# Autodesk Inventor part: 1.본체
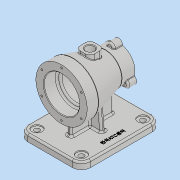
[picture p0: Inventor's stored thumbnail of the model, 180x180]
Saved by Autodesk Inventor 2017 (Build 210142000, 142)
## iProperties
Part Number: 1.본체
Material: 일반
Document SubType Name: Modeling
Designer: user
Density: 1 g/cm^3
Appearance: 기본값
Author: user
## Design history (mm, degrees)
sketch "스케치1"
  geometry: L1 (-50, 0)-(50, 0); L2 (-50, 0)-(-50, 45); L3 (-50, 45)-(-30, 45); L4 (-30, 45)-(27, 29); L5 (27, 29)-(50, 29); L6 (50, 29)-(50, 0); 2 further points
  constraints: 12 end point, 2 perpendicular, 1 coincident, 1 horizontal, 1 midpoint, 1 parallel, 1 vertical
  dimensions: "d0" = 100 distance of L1.start L1.end; "d1" = 45 distance of L1.start L2.end; "d2" = 20 distance of L2.end L3.end; "d3" = 58 diameter of L5 L1; "d4" = 23 distance of L4.end L5.end
revolve "회전1" sketch "스케치1" stored, may be unused: angle "d5" = 90 deg
node "작업 평면1"
sketch "스케치5" dims "d100" = 16
  geometry: L1 (-70, -55)-(70, -55); L2 (70, -55)-(70, 55); L3 (70, 55)-(-70, 55); L4 (-70, 55)-(-70, -55); L5 (-70, -55)-(70, 55); L6 (70, -55)-(-70, 55); 1 further point
  constraints: 12 end point, 2 midpoint, 2 parallel, 1 horizontal, 1 perpendicular
  dimensions: "d34" = 140 distance of L3.end L2.end; "d35" = 110 distance of L2.end L1.end
extrude "돌출2" join sketch "스케치5" distance "d36" = 12; taper "d37" = 0 deg
sketch "스케치6"
  geometry: L1 (-37, -4)-(37, -4); L2 (37, -4)-(37, 4); L3 (37, 4)-(-37, 4); L4 (-37, 4)-(-37, -4); L5 (-37, -4)-(37, 4); L6 (37, -4)-(-37, 4); 1 further point
  constraints: 12 end point, 2 midpoint, 2 parallel, 1 horizontal, 1 perpendicular
  dimensions: "d38" = 74 distance of L3.end L2.end; "d39" = 8 distance of L2.end L1.end
extrude "돌출3" join sketch "스케치6" distance "d40" = 82; taper "d41" = 0 deg
sketch "스케치7"
  geometry: L1 (-70, -55)-(-70, 55) reference; L2 (0, 0)-(-70, 0); L3 (-70, 0)-(-70, -24); L4 (-70, -24)-(-4.155, -18.239); L5 (-70, 0)-(-70, 24); L6 (-70, 24)-(-4.155, 18.239); L7 (-4.155, 18.239)-(-4.155, -18.239)
  constraints: 12 end point, 2 point on line, 1 midpoint, 1 vertical
  dimensions: "d42" = 24 distance of L2.end L3.end; "d43" = 24 distance of L2.end L5.end; "d44" = 95 deg angle of L1 L6; "d45" = 95 deg angle of L1 L4; "d46" = 36.47868 distance of L6.end L4.end
extrude "돌출4" join sketch "스케치7" stored distance "d47" = 8; taper "d48" = 0 deg
sketch "스케치8"
  geometry: L1 (0, 0)-(0, 29); L2 (0, 0)-(25.115, -14.5); L3 (0, 0)-(-25.115, -14.5); C1 r 7 at (0, 29); C2 r 7 at (25.115, -14.5); C3 r 7 at (-25.115, -14.5); A1 r 29 centre (0, 0) between (4, -28.723) and (-4, -28.723) reference; A2 r 29 centre (0, 0) between (0, 29) and (25.115, -14.5)
  constraints: 6 end point, 6 point on circle, 4 centre point, 4 coincident
  dimensions: "d49" = 120 deg angle of L2 L1; "d50" = 120 deg angle of L2 L3; "d51" = 14 diameter of C1; "d52" = 14 diameter of C2; "d53" = 14 diameter of C3
extrude "돌출5" join sketch "스케치8" distance "d54" = 15; taper "d55" = 0 deg
sketch "스케치9"
  geometry: A1 r 7 centre (25.115, -43.5) between (20.909, -49.095) and (27.858, -37.06) reference; A2 r 7 centre (-25.115, -43.5) between (-27.858, -37.06) and (-20.909, -49.095) reference; 3 further points
  constraints: 2 coincident
hole "구멍3" sketch "스케치9" at (0, 0), (25.115, -43.5), (-25.115, -43.5) diameter "d56" = 3.242; stored, may be unused: countersink angle "d60" = 90 deg, drill point angle "d62" = 118 deg; dims "d57" = 9, "d58" = 4, "d59" = 2, "d61" = 11
sketch "스케치10"
  geometry: L1 (0, 40)-(0, -40); L2 (-34.641, 20)-(34.641, -20); L3 (-34.641, -20)-(34.641, 20); L4 (0, -40)-(0, 40); L5 (34.641, -20)-(-34.641, 20); L6 (34.641, 20)-(-34.641, -20); C1 r 45 at (0, 0) reference; C2 r 40 at (0, 0); 18 further points
  constraints: 14 coincident, 12 end point, 1 centre point, 1 midpoint, 1 vertical, 37 other
  dimensions: "d63" = 80 diameter of C2; "d64" = 80 distance of L1.start L1.end; "d67" = 360 deg dimension on C1.centre point (0, 40) (derived)
hole "구멍4" sketch "스케치10" at (0, 40), (0, -40), (-34.641, 20), (34.641, -20), (-34.641, -20), (34.641, 20) diameter "d69" = 3.242; stored, may be unused: countersink angle "d73" = 90 deg, drill point angle "d75" = 118 deg; dims "d70" = 9, "d71" = 4, "d72" = 2, "d74" = 11
sketch "스케치11"
  geometry: L1 (-50, -45)-(-50, 45) reference; L2 (-50, 0)-(50, 0); L3 (50, -8.06)-(50, 28.155) reference; L4 (-50, 0)-(-50, 31); L5 (-50, 31)-(-27, 31); L6 (-27, 31)-(-27, 25); L7 (-27, 25)-(20, 25); L8 (20, 25)-(20, 19); L9 (20, 19)-(50, 19); L10 (50, 0)-(50, 19); 1 further point
  constraints: 16 end point, 5 perpendicular, 3 point on line, 1 collinear, 1 horizontal, 1 midpoint
  dimensions: "d76" = 31 distance of L2.start L4.end; "d77" = 23 distance of L4.end L5.end; "d78" = 47 distance of L6.end L7.end; "d79" = 50 diameter of L7 L2; "d80" = 38 diameter of L9 L2
revolve "회전2" sketch "스케치11" stored, may be unused: angle "d81" = 90 deg
node "작업 평면2"
sketch "스케치12"
  geometry: L1 (-12.5, -12.5)-(12.5, -12.5); L2 (12.5, -12.5)-(12.5, 12.5); L3 (12.5, 12.5)-(-12.5, 12.5); L4 (-12.5, 12.5)-(-12.5, -12.5); L5 (-12.5, -12.5)-(12.5, 12.5); L6 (12.5, -12.5)-(-12.5, 12.5); 1 further point
  constraints: 12 end point, 2 midpoint, 2 parallel, 1 horizontal, 1 perpendicular
  dimensions: "d83" = 25 distance of L3.end L2.end; "d84" = 25 distance of L2.end L1.end
extrude "돌출6" join sketch "스케치12" stored distance "d85" = 15; taper "d86" = 0 deg
sketch "스케치13"
  geometry: C1 r 7.5 at (0, 0); 1 further point
  constraints: 1 centre point, 1 coincident
  dimensions: "d87" = 15 diameter of C1
extrude "돌출7" cut sketch "스케치13" stored distance "d88" = 0; taper "d89" = 0 deg
fillet "모깎기1" dims "d90" = 8
chamfer "모따기1" distance "d91" = 1; stored, may be unused: second distance "d92" = 2, angle "d93" = 45 deg
fillet "모깎기2" dims "d94" = 3
fillet "모깎기3" dims "d95" = 1
fillet "모깎기4" dims "d96" = 3
fillet "모깎기5" dims "d97" = 3
fillet "모깎기6" dims "d98" = 3
fillet "모깎기7" dims "d99" = 3
fillet "모깎기8" dims "d100" = 16
sketch "스케치14"
  geometry: A1 r 16 centre (-54, -39) between (-70, -39) and (-54, -55) reference; A2 r 16 centre (54, -39) between (54, -55) and (70, -39) reference; A3 r 16 centre (54, 39) between (70, 39) and (54, 55) reference; A4 r 16 centre (-54, 39) between (-54, 55) and (-70, 39) reference; 5 further points
  constraints: 4 coincident
hole "구멍5" sketch "스케치14" at (54, 39), (54, -39), (-54, -39), (-54, 39) diameter "d101" = 9; stored, may be unused: countersink angle "d105" = 90 deg, drill point angle "d107" = 118 deg; dims "d102" = 9, "d103" = 18, "d104" = 2, "d106" = 30
fillet "모깎기9" dims "d108" = 3
chamfer "모따기2" distance "d109" = 1; stored, may be unused: second distance "d110" = 2, angle "d111" = 45 deg
chamfer "모따기3" distance "d112" = 1; stored, may be unused: second distance "d113" = 2, angle "d114" = 45 deg
sketch "스케치15"
  geometry: L1 (-7, 20.726)-(-7, 7) reference; L2 (1, 26.749)-(-1, 26.749) reference; L3 (7, 7)-(7, 20.726) reference; L4 (34, 7)-(7, 7) reference; L5 (40, -1)-(40, 1) reference; L6 (7, -7)-(34, -7) reference; L7 (7, -20.726)-(7, -7) reference; L8 (-1, -26.749)-(1, -26.749) reference; L9 (-7, -7)-(-7, -20.726) reference; L10 (-34, -7)-(-7, -7) reference; L11 (-40, 1)-(-40, -1) reference; L12 (-7, 7)-(-34, 7) reference; L13 (-54, -55)-(54, -55) reference; L14 (70, -39)-(70, 39) reference; L15 (54, 55)-(-54, 55) reference; L16 (-70, 39)-(-70, -39) reference; C1 r 9 at (-54, -39) reference; C2 r 9 at (54, 39) reference; C3 r 9 at (54, -39) reference; C4 r 9 at (-54, 39) reference; A1 r 6 centre (34, 1) between (40, 1) and (34, 7) reference; A2 r 6 centre (34, -1) between (34, -7) and (40, -1) reference; A3 r 6 centre (-34, -1) between (-40, -1) and (-34, -7) reference; A4 r 6 centre (-34, 1) between (-34, 7) and (-40, 1) reference; A5 r 16 centre (-54, -39) between (-70, -39) and (-54, -55) reference; A6 r 16 centre (54, -39) between (54, -55) and (70, -39) reference; A7 r 16 centre (54, 39) between (70, 39) and (54, 55) reference; A8 r 16 centre (-54, 39) between (-54, 55) and (-70, 39) reference; 5 further points; 4 other entities
  constraints: 4 other
sketch "스케치16"
  geometry: L1 (-70, -70)-(-70, -82) reference; L2 (-50, -45)-(-50, 45) reference; L3 (-37, -47.99)-(-37, -67) reference; L4 (37, -67)-(37, -31.984) reference; 1 further point
  dimensions: "d115" = 20 distance between parallel lines of L1 L2 (derived); "d116" = 33 distance between parallel lines of L1 L3 (derived); "d117" = 74 distance between parallel lines of L4 L3 (derived)
fillet "모깎기10" dims "d118" = 3
node "작업 평면3"
sketch "스케치17"
  geometry: L1 (54, 55)-(-54, 55) reference; L2 (0, 55)-(0, 40); 3 further points
  constraints: 2 coincident, 2 end point, 1 midpoint, 1 vertical, 1 other
  dimensions: "d120" = 15 distance of L2.start L2.end
feature "엠보싱1" sketch "스케치17" dims "d0" = 100, "d1" = 45, "d2" = 20, "d3" = 58, "d4" = 23, "d121" = 0.5, "d122" = 0
fillet "모깎기11" dims "d123" = 1
sketch "스케치18"
  geometry: L1 (0, -29)-(0, 26.077); L2 (0, -29)-(-47.698, -56.538); C1 r 1.621 at (-25.115, -43.5) reference; C2 r 1.621 at (0, 0) reference; C3 r 1.621 at (25.115, -43.5) reference; C4 r 20 at (0, -29) reference; A1 r 29 centre (0, -29) between (-20.339, -49.672) and (20.339, -49.672) reference; A2 r 1 centre (21.04, -50.385) between (21.55, -49.524) and (20.339, -49.672) reference; A3 r 7 centre (25.115, -43.5) between (21.55, -49.524) and (28.549, -37.4) reference; A4 r 1 centre (29.04, -36.529) between (28.072, -36.278) and (28.549, -37.4) reference; A5 r 29 centre (0, -29) between (28.072, -36.278) and (7.733, -1.05) reference; A6 r 1 centre (8, -0.086) between (7, -0.075) and (7.733, -1.05) reference; A7 r 7 centre (0, 0) between (7, -0.075) and (-7, -0.075) reference; A8 r 1 centre (-8, -0.086) between (-7.733, -1.05) and (-7, -0.075) reference; A9 r 29 centre (0, -29) between (-7.733, -1.05) and (-28.072, -36.278) reference; A10 r 1 centre (-29.04, -36.529) between (-28.549, -37.4) and (-28.072, -36.278) reference; A11 r 7 centre (-25.115, -43.5) between (-28.549, -37.4) and (-21.55, -49.524) reference; A12 r 1 centre (-21.04, -50.385) between (-20.339, -49.672) and (-21.55, -49.524) reference
  constraints: 4 end point, 1 equal length, 1 point on line, 1 vertical
  dimensions: "d128" = 120 deg angle of L2 L1 (derived); "d129" = 55.07668 distance of L1.start L1.end
node "솔리드1"
other parameters: "d33" = -82, "d82" = 45, "d119" = -62.5
